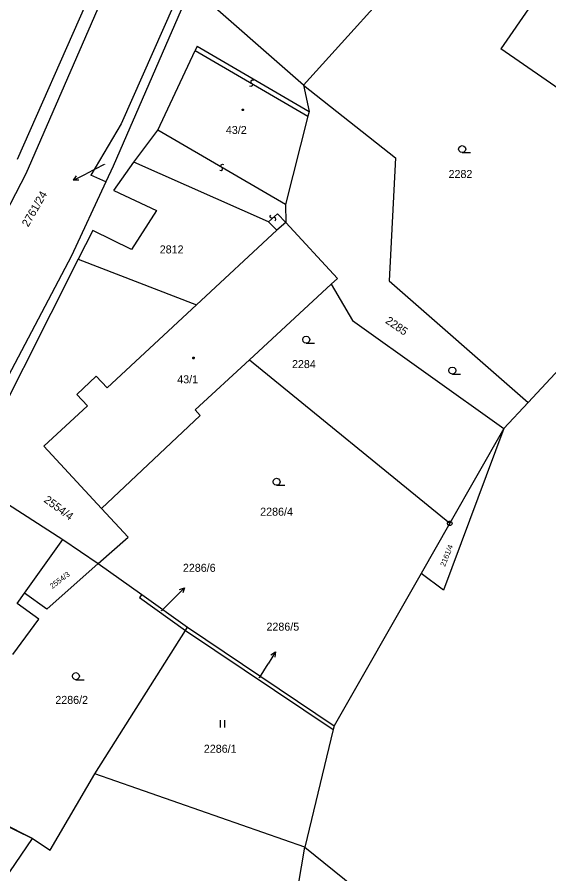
# Model space of a CAD drawing. Extents: x -747792 to -745414, y -1093712 to -1091463.
# Drawn here: x -746629.3 to -746572.8, y -1093057.2 to -1092966.2 of the extents above; entities that cross this region are included whole.
import ezdxf

# ---------------------------------------------------------------- set-up
doc = ezdxf.new("R2010")
doc.units = 0
for name, color, linetype in [('Pracovní_bod JDTM STC_VC', 7, 'Continuous'), ('Pracovní_bod JDTM STC_VC - výška', 7, 'Continuous'), ('Pracovní_bod JDTM STC_VC - číslo', 7, 'Continuous'), ('Pracovní_bod NN - výška', 7, 'Continuous'), ('Pracovní_bod polohopisu', 7, 'Continuous'), ('Pracovní_bod polohopisu - výška', 7, 'Continuous'), ('Pracovní_bod VN - výška', 7, 'Continuous')]:
    doc.layers.add(name, color=color, linetype=linetype)

msp = doc.modelspace()

# ---------------------------------------------------------------- linework, layer by layer
at = {"layer": 'Pracovní_bod JDTM STC_VC - výška'}
for points in [[(-746605.27, -1092975.995), (-746605.22, -1092976.005), (-746605.195, -1092976.05), (-746605.185, -1092976.08), (-746605.195, -1092976.125), (-746605.235, -1092976.16), (-746605.27, -1092976.165), (-746605.315, -1092976.15), (-746605.345, -1092976.12), (-746605.355, -1092976.08), (-746605.345, -1092976.035), (-746605.305, -1092976)], [(-746610.51, -1093002.355), (-746610.46, -1093002.365), (-746610.435, -1093002.41), (-746610.425, -1093002.44), (-746610.435, -1093002.485), (-746610.475, -1093002.52), (-746610.51, -1093002.525), (-746610.555, -1093002.51), (-746610.585, -1093002.48), (-746610.595, -1093002.44), (-746610.585, -1093002.395), (-746610.545, -1093002.36)]]:
    msp.add_lwpolyline(points, close=True, dxfattribs=at)
at = {"layer": 'Pracovní_bod JDTM STC_VC - číslo'}
for points in [[(-746581.98, -1092980.62), (-746582.17, -1092980.57), (-746582.305, -1092980.43), (-746582.355, -1092980.245), (-746582.305, -1092980.06), (-746582.17, -1092979.92), (-746581.98, -1092979.87), (-746581.79, -1092979.92), (-746581.655, -1092980.06), (-746581.605, -1092980.245), (-746581.655, -1092980.43), (-746581.79, -1092980.57), (-746581.98, -1092980.62), (-746581.105, -1092980.62)], [(-746598.55, -1093000.86), (-746598.74, -1093000.81), (-746598.875, -1093000.67), (-746598.925, -1093000.485), (-746598.875, -1093000.3), (-746598.74, -1093000.16), (-746598.55, -1093000.11), (-746598.36, -1093000.16), (-746598.225, -1093000.3), (-746598.175, -1093000.485), (-746598.225, -1093000.67), (-746598.36, -1093000.81), (-746598.55, -1093000.86), (-746597.675, -1093000.86)], [(-746583.02, -1093004.15), (-746583.21, -1093004.1), (-746583.345, -1093003.96), (-746583.395, -1093003.775), (-746583.345, -1093003.59), (-746583.21, -1093003.45), (-746583.02, -1093003.4), (-746582.83, -1093003.45), (-746582.695, -1093003.59), (-746582.645, -1093003.775), (-746582.695, -1093003.96), (-746582.83, -1093004.1), (-746583.02, -1093004.15), (-746582.145, -1093004.15)], [(-746601.7, -1093015.96), (-746601.89, -1093015.91), (-746602.025, -1093015.77), (-746602.075, -1093015.585), (-746602.025, -1093015.4), (-746601.89, -1093015.26), (-746601.7, -1093015.21), (-746601.51, -1093015.26), (-746601.375, -1093015.4), (-746601.325, -1093015.585), (-746601.375, -1093015.77), (-746601.51, -1093015.91), (-746601.7, -1093015.96), (-746600.825, -1093015.96)], [(-746623.02, -1093036.61), (-746623.21, -1093036.56), (-746623.345, -1093036.42), (-746623.395, -1093036.235), (-746623.345, -1093036.05), (-746623.21, -1093035.91), (-746623.02, -1093035.86), (-746622.83, -1093035.91), (-746622.695, -1093036.05), (-746622.645, -1093036.235), (-746622.695, -1093036.42), (-746622.83, -1093036.56), (-746623.02, -1093036.61), (-746622.145, -1093036.61)], [(-746607.7, -1093040.92), (-746607.7, -1093041.67)], [(-746607.2, -1093041.67), (-746607.2, -1093040.92)]]:
    msp.add_lwpolyline(points, dxfattribs=at)
at = {"layer": 'Pracovní_bod NN - výška'}
for points in [[(-746616.96, -1092956.74), (-746628.34, -1092982.88)], [(-746586.42, -1092959.67), (-746598.85, -1092973.44)], [(-746610.76, -1092962.98), (-746619.05, -1092982.07)], [(-746611.48, -1092962.35), (-746618.21, -1092977.55)], [(-746598.85, -1092973.44), (-746610.76, -1092962.98)], [(-746622.01, -1092964.92), (-746629.27, -1092981.35)], [(-746574.63, -1092964.9), (-746577.88, -1092969.58)], [(-746610.12, -1092969.31), (-746610.33, -1092969.76)], [(-746610.12, -1092969.31), (-746598.23, -1092976.27)], [(-746570.65, -1092974.6), (-746577.88, -1092969.58)], [(-746614.3, -1092978.23), (-746610.33, -1092969.76)], [(-746598.85, -1092973.44), (-746598.23, -1092976.27)], [(-746598.85, -1092973.44), (-746589.08, -1092981.17)], [(-746598.36, -1092976.75), (-746600.76, -1092986.14)], [(-746598.23, -1092976.27), (-746598.36, -1092976.75)], [(-746618.21, -1092977.55), (-746621.44, -1092983.01)], [(-746616.86, -1092981.63), (-746614.3, -1092978.23)], [(-746589.08, -1092981.17), (-746589.74, -1092994.23)], [(-746619.05, -1092982.07), (-746619.82, -1092983.71)], [(-746618.98, -1092984.65), (-746616.86, -1092981.63)], [(-746602.56, -1092987.98), (-746616.86, -1092981.63)], [(-746628.34, -1092982.88), (-746641.93, -1093009.12)], [(-746619.82, -1092983.71), (-746621.44, -1092983.01)], [(-746619.82, -1092983.71), (-746623.48, -1092991.57)], [(-746618.98, -1092984.65), (-746614.45, -1092986.77)], [(-746614.45, -1092986.77), (-746617.11, -1092990.91)], [(-746600.76, -1092986.14), (-746600.73, -1092988.04)], [(-746601.66, -1092988.87), (-746602.56, -1092987.98)], [(-746600.73, -1092988.04), (-746601.66, -1092988.87)], [(-746600.73, -1092988.04), (-746595.23, -1092993.99)], [(-746621.22, -1092988.91), (-746622.77, -1092991.94)], [(-746617.11, -1092990.91), (-746621.22, -1092988.91)], [(-746601.66, -1092988.87), (-746610.19, -1092996.78)], [(-746623.48, -1092991.57), (-746635.57, -1093014.47)], [(-746622.77, -1092991.94), (-746634.45, -1093015.09)], [(-746622.77, -1092991.94), (-746610.19, -1092996.78)], [(-746561.68, -1092992.9), (-746574.97, -1093007.15)], [(-746595.89, -1092994.6), (-746595.23, -1092993.99)], [(-746595.89, -1092994.6), (-746604.59, -1093002.65)], [(-746595.89, -1092994.6), (-746593.63, -1092998.47)], [(-746589.74, -1092994.23), (-746574.97, -1093007.15)], [(-746610.19, -1092996.78), (-746619.71, -1093005.59)], [(-746593.63, -1092998.47), (-746577.55, -1093009.92)], [(-746604.59, -1093002.65), (-746610.34, -1093007.96)], [(-746604.59, -1093002.65), (-746583.3, -1093020)], [(-746620.85, -1093004.36), (-746622.93, -1093006.31)], [(-746619.71, -1093005.59), (-746620.85, -1093004.36)], [(-746622.93, -1093006.31), (-746621.8, -1093007.53)], [(-746621.8, -1093007.53), (-746626.42, -1093011.8)], [(-746574.97, -1093007.15), (-746577.55, -1093009.92)], [(-746620.31, -1093018.41), (-746609.8, -1093008.55)], [(-746610.34, -1093007.96), (-746609.8, -1093008.55)], [(-746577.55, -1093009.92), (-746583.98, -1093027.11)], [(-746577.55, -1093009.92), (-746583.3, -1093020)], [(-746620.31, -1093018.41), (-746626.42, -1093011.8)], [(-746630.27, -1093017.93), (-746624.42, -1093021.7)], [(-746620.31, -1093018.41), (-746617.48, -1093021.47)], [(-746583.3, -1093020), (-746586.34, -1093025.32)], [(-746628.48, -1093027.42), (-746624.42, -1093021.7)], [(-746624.42, -1093021.7), (-746620.66, -1093024.28)], [(-746620.66, -1093024.28), (-746617.48, -1093021.47)], [(-746620.66, -1093024.28), (-746626.11, -1093029.1)], [(-746620.66, -1093024.28), (-746616.02, -1093027.57)], [(-746586.34, -1093025.32), (-746595.58, -1093041.5)], [(-746583.98, -1093027.11), (-746586.34, -1093025.32)], [(-746629.25, -1093028.5), (-746628.48, -1093027.42)], [(-746626.11, -1093029.1), (-746628.48, -1093027.42)], [(-746616.02, -1093027.57), (-746616.27, -1093027.88)], [(-746616.02, -1093027.57), (-746611.15, -1093031.03)], [(-746626.95, -1093030.17), (-746629.25, -1093028.5)], [(-746616.27, -1093027.88), (-746611.37, -1093031.38)], [(-746629.7, -1093033.95), (-746626.95, -1093030.17)], [(-746620.99, -1093046.6), (-746611.37, -1093031.38)], [(-746611.37, -1093031.38), (-746611.15, -1093031.03)], [(-746611.37, -1093031.38), (-746595.68, -1093041.9)], [(-746611.15, -1093031.03), (-746595.58, -1093041.5)], [(-746595.68, -1093041.9), (-746598.7, -1093054.4)], [(-746595.58, -1093041.5), (-746595.68, -1093041.9)], [(-746625.75, -1093054.73), (-746620.99, -1093046.6)], [(-746598.7, -1093054.4), (-746620.99, -1093046.6)], [(-746634.9, -1093049.93), (-746627.61, -1093053.49)], [(-746627.61, -1093053.49), (-746634.31, -1093050.11)], [(-746642.63, -1093075.5), (-746627.61, -1093053.49)], [(-746627.61, -1093053.49), (-746625.75, -1093054.73)], [(-746599.4, -1093058.58), (-746598.7, -1093054.4)], [(-746598.7, -1093054.4), (-746579.06, -1093070.24)]]:
    msp.add_lwpolyline(points, dxfattribs=at)
at = {"layer": 'Pracovní_bod polohopisu'}
for points in [[(-746610.33, -1092969.76), (-746598.36, -1092976.75)], [(-746604.134, -1092972.944), (-746604.289, -1092972.911), (-746604.419, -1092973.015), (-746604.427, -1092973.167), (-746604.262, -1092973.361), (-746604.281, -1092973.512), (-746604.415, -1092973.602), (-746604.556, -1092973.566)], [(-746600.76, -1092986.14), (-746614.3, -1092978.23)], [(-746607.741, -1092982.496), (-746607.586, -1092982.529), (-746607.456, -1092982.425), (-746607.448, -1092982.273), (-746607.613, -1092982.079), (-746607.594, -1092981.928), (-746607.46, -1092981.838), (-746607.319, -1092981.874)], [(-746601.59, -1092987.13), (-746602.56, -1092987.98)], [(-746601.847, -1092987.853), (-746601.767, -1092987.717), (-746601.824, -1092987.561), (-746601.965, -1092987.505), (-746602.202, -1092987.6), (-746602.339, -1092987.534), (-746602.382, -1092987.379), (-746602.303, -1092987.257)], [(-746601.59, -1092987.13), (-746600.73, -1092988.04)]]:
    msp.add_lwpolyline(points, dxfattribs=at)
at = {"layer": 'Pracovní_bod polohopisu - výška'}
for points in [[(-746620.01, -1092981.89), (-746621.94, -1092982.87)], [(-746623.278, -1092983.549), (-746621.94, -1092982.87)], [(-746622.719, -1092983.546), (-746623.278, -1092983.549), (-746622.945, -1092983.1)], [(-746611.469, -1093026.85), (-746612.53, -1093027.91)], [(-746611.999, -1093027.026), (-746611.469, -1093026.85), (-746611.646, -1093027.38)], [(-746613.92, -1093029.3), (-746612.53, -1093027.91)], [(-746601.821, -1093033.658), (-746602.6, -1093034.94)], [(-746602.294, -1093033.956), (-746601.821, -1093033.658), (-746601.867, -1093034.215)], [(-746603.5, -1093036.42), (-746602.6, -1093034.94)]]:
    msp.add_lwpolyline(points, dxfattribs=at)
at = {"layer": 'Pracovní_bod VN - výška'}
msp.add_lwpolyline([(-746583.225, -1093019.76), (-746583.1, -1093019.855), (-746583.05, -1093020), (-746583.1, -1093020.145), (-746583.225, -1093020.24), (-746583.375, -1093020.24), (-746583.5, -1093020.145), (-746583.55, -1093020), (-746583.5, -1093019.855), (-746583.375, -1093019.76)], close=True, dxfattribs=at)
msp.add_lwpolyline([(-746583.325, -1093020), (-746583.275, -1093020)], dxfattribs=at)

# ---------------------------------------------------------------- texts
at = {"layer": 'Pracovní_bod JDTM STC_VC'}
for s, height, p in [('43/2', 0.85, (-746607.082, -1092978.64)), ('2761/24', 0.05, (-746620.144, -1092981.89)), ('2282', 0.85, (-746583.426, -1092983.32)), ('2812', 0.85, (-746614.11, -1092991.33)), ('2284', 0.85, (-746600.059, -1093003.51)), ('43/1', 0.85, (-746612.251, -1093005.13)), ('2286/4', 0.85, (-746603.438, -1093019.19)), ('2286/6', 0.05, (-746614.046, -1093029.3)), ('2286/5', 0.05, (-746603.628, -1093036.42)), ('2286/2', 0.85, (-746625.205, -1093039.18)), ('2286/1', 0.85, (-746609.424, -1093044.37))]:
    msp.add_text(s, height=height, dxfattribs=at).set_placement(p)
for s, height, rotation, p in [('2285', 0.85, 325.49732, (-746590.21, -1092998.659)), ('2554/4', 0.85, 323.72115, (-746626.489, -1093017.671)), ('2161/4', 0.57, 68.46846, (-746583.811, -1093024.652)), ('2554/3', 0.57, 37.01307, (-746625.522, -1093026.983))]:
    msp.add_text(s, height=height, rotation=rotation, dxfattribs=at).set_placement(p)
at = {"layer": 'Pracovní_bod polohopisu - výška'}
msp.add_text('2761/24', height=0.85, rotation=60.04598, dxfattribs=at).set_placement((-746628.086, -1092988.585))
for s, p in [('2286/6', (-746611.648, -1093025.15)), ('2286/5', (-746602.772, -1093031.4))]:
    msp.add_text(s, height=0.85, dxfattribs=at).set_placement(p)

doc.saveas('drawing.dxf')
